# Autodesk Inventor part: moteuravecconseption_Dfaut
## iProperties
Created: 2007-07
Part Number: moteuravecconseption_Dfaut
Document SubType Name: Modeling
Designer: EF
Density: 1 g/cm^3
Author: EF
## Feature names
1. Base1
